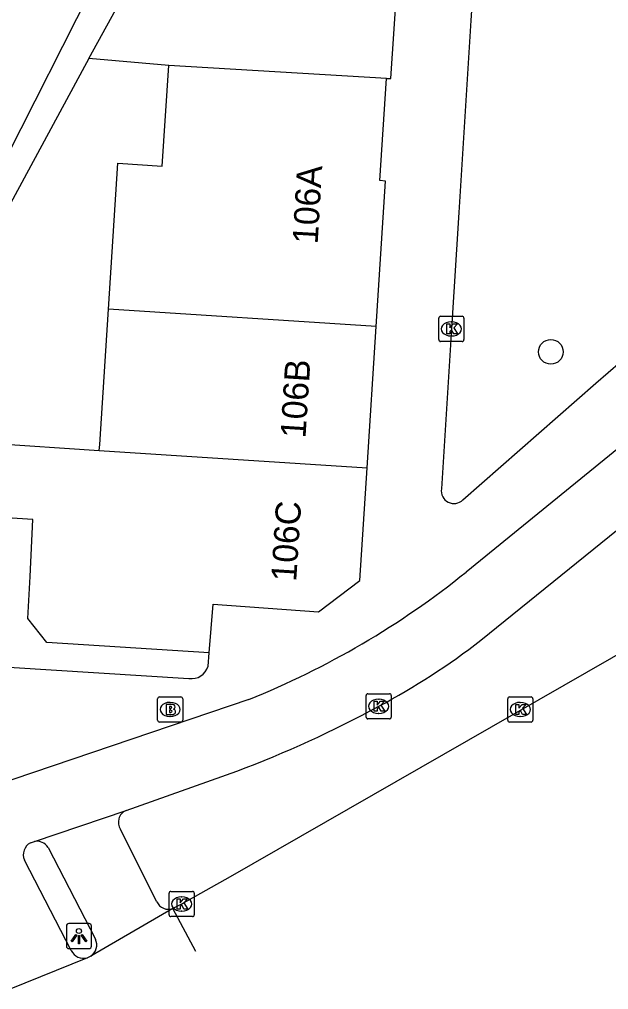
# Model space of a CAD drawing. Extents: x 159961 to 160856, y 382704 to 383353.
# Drawn here: x 160545.75 to 160569.17, y 382711.52 to 382750.05 of the extents above; entities that cross this region are included whole.
import ezdxf

# ---------------------------------------------------------------- set-up
doc = ezdxf.new("R2010")
doc.units = 0
for name, color, linetype in [('IMGEO_Boom', 7, 'Continuous'), ('IMGEO_Brandkraan', 7, 'Continuous'), ('IMGEO_Fietspad_gesloten', 7, 'Continuous'), ('IMGEO_Kolk', 7, 'Continuous'), ('IMGEO_Lichtpunt', 7, 'Continuous'), ('IMGEO_Pand', 7, 'Continuous'), ('IMGEO_Pand_nummerreeks', 7, 'Continuous'), ('IMGEO_Rijbaan_lokaal_gesloten', 7, 'Continuous'), ('IMGEO_Voetpad_open', 7, 'Continuous')]:
    doc.layers.add(name, color=color, linetype=linetype)

msp = doc.modelspace()

# ---------------------------------------------------------------- linework, layer by layer
at = {"layer": 'IMGEO_Boom'}
msp.add_circle((160566.873, 382736.846), 0.489, dxfattribs=at)
at = {"layer": 'IMGEO_Brandkraan'}
for p, q in [((160551.315, 382723.144), (160552.167, 382723.144)), ((160551.24, 382722.218), (160551.24, 382723.07)), ((160551.728, 382722.924), (160551.753, 382722.924)), ((160552.241, 382723.07), (160552.241, 382722.218)), ((160551.751, 382722.364), (160551.726, 382722.364)), ((160552.167, 382722.144), (160551.315, 382722.144))]:
    msp.add_line(p, q, dxfattribs=at)
for points in [[(160551.315, 382723.144), (160552.167, 382723.144)], [(160551.24, 382722.218), (160551.24, 382723.07)], [(160551.588, 382722.844), (160551.588, 382722.444), (160551.801, 382722.444)], [(160551.819, 382722.844), (160551.588, 382722.844)], [(160551.767, 382722.763), (160551.713, 382722.763), (160551.713, 382722.687)], [(160552.241, 382723.07), (160552.241, 382722.218)], [(160551.713, 382722.687), (160551.766, 382722.687)], [(160551.775, 382722.611), (160551.713, 382722.611), (160551.713, 382722.53)], [(160551.713, 382722.53), (160551.775, 382722.53)], [(160552.167, 382722.144), (160551.315, 382722.144)]]:
    msp.add_lwpolyline(points, dxfattribs=at)
for centre, radius, start, end in [((160551.317, 382723.068), 0.0765, 91.552, 178.448), ((160551.317, 382723.068), 0.0765, 91.552, 178.448), ((160552.165, 382723.068), 0.0765, 1.552, 88.448), ((160552.165, 382723.068), 0.0765, 1.552, 88.448), ((160551.768, 382722.725), 0.0379, 267.8285, 90.9355), ((160551.823, 382722.699), 0.145, 59.4692, 91.5367), ((160551.848, 382722.746), 0.0922, 285.5137, 58.1501), ((160551.776, 382722.57), 0.0404, 269.8759, 90.5077), ((160551.807, 382722.695), 0.251, 268.6676, 293.5347), ((160551.853, 382722.554), 0.105, 301.3115, 78.989), ((160551.317, 382722.22), 0.0765, 181.552, 268.448), ((160551.317, 382722.22), 0.0765, 181.552, 268.448), ((160552.165, 382722.22), 0.0765, 271.552, 358.448), ((160552.165, 382722.22), 0.0765, 271.552, 358.448)]:
    msp.add_arc(centre, radius, start, end, dxfattribs=at)
for centre, major_axis, ratio, start_param, end_param in [((160551.727, 382722.644), (-0.387, 0.002), 0.722429, 4.712389, 7.853982), ((160551.752, 382722.644), (-0.39, 0.002), 0.717154, 1.570796, 4.712389)]:
    msp.add_ellipse(centre, major_axis=major_axis, ratio=ratio, start_param=start_param, end_param=end_param, dxfattribs=at)
at = {"layer": 'IMGEO_Fietspad_gesloten'}
for points in [[(160579.704, 382739.971), (160571.274, 382734.411), (160563.508, 382728.101)], [(160564.089, 382725.394), (160572.382, 382732.089), (160574.211, 382733.38)], [(160554.866, 382723.034), (160541.601, 382718.558)], [(160549.988, 382718.627), (160554.394, 382720.196)], [(160546.35, 382717.404), (160549.988, 382718.627)], [(160546.188, 382717.349), (160546.35, 382717.404)], [(160547.813, 382713.074), (160545.95, 382716.662)]]:
    msp.add_lwpolyline(points, dxfattribs=at)
for centre, radius, start, end in [((160541.972, 382754.929), 34.403, 292.0121, 308.756), ((160546.643, 382747.925), 28.496, 298.0235, 307.7518), ((160538.317, 382762.865), 45.597, 290.6463, 298.4391), ((160546.439, 382716.877), 0.534, 118.0052, 203.7792), ((160548.297, 382713.29), 0.53, 204.0897, 286.8736)]:
    msp.add_arc(centre, radius, start, end, dxfattribs=at)
at = {"layer": 'IMGEO_Kolk'}
for p, q in [((160562.419, 382737.331), (160562.419, 382738.183)), ((160562.494, 382738.257), (160563.346, 382738.257)), ((160563.42, 382738.183), (160563.42, 382737.331)), ((160562.907, 382738.037), (160562.932, 382738.037)), ((160562.93, 382737.477), (160562.905, 382737.477)), ((160563.346, 382737.257), (160562.494, 382737.257)), ((160559.53, 382722.344), (160559.53, 382723.196)), ((160559.605, 382723.27), (160560.457, 382723.27)), ((160560.531, 382723.196), (160560.531, 382722.344)), ((160565.233, 382723.144), (160566.085, 382723.144)), ((160560.018, 382723.05), (160560.043, 382723.05)), ((160565.158, 382722.218), (160565.158, 382723.07)), ((160565.646, 382722.924), (160565.671, 382722.924)), ((160566.159, 382723.07), (160566.159, 382722.218)), ((160560.041, 382722.49), (160560.016, 382722.49)), ((160565.669, 382722.364), (160565.644, 382722.364)), ((160560.457, 382722.27), (160559.605, 382722.27)), ((160566.085, 382722.144), (160565.233, 382722.144)), ((160551.773, 382715.417), (160552.625, 382715.417)), ((160551.698, 382714.491), (160551.698, 382715.343)), ((160552.186, 382715.197), (160552.211, 382715.197)), ((160552.699, 382715.343), (160552.699, 382714.491)), ((160552.209, 382714.637), (160552.184, 382714.637)), ((160552.625, 382714.417), (160551.773, 382714.417))]:
    msp.add_line(p, q, dxfattribs=at)
for points in [[(160562.419, 382737.331), (160562.419, 382738.183)], [(160562.494, 382738.257), (160563.346, 382738.257)], [(160563.42, 382738.183), (160563.42, 382737.331)], [(160562.74, 382737.957), (160562.863, 382737.957), (160562.863, 382737.806), (160562.993, 382737.957), (160563.157, 382737.957), (160563.011, 382737.806), (160563.164, 382737.557), (160563.012, 382737.557), (160562.927, 382737.721), (160562.863, 382737.654), (160562.863, 382737.557), (160562.74, 382737.557), (160562.74, 382737.957)], [(160563.346, 382737.257), (160562.494, 382737.257)], [(160559.53, 382722.344), (160559.53, 382723.196)], [(160559.605, 382723.27), (160560.457, 382723.27)], [(160560.531, 382723.196), (160560.531, 382722.344)], [(160565.233, 382723.144), (160566.085, 382723.144)], [(160559.851, 382722.97), (160559.974, 382722.97), (160559.974, 382722.819), (160560.104, 382722.97), (160560.268, 382722.97), (160560.122, 382722.819), (160560.275, 382722.57), (160560.123, 382722.57), (160560.038, 382722.734), (160559.974, 382722.667), (160559.974, 382722.57), (160559.851, 382722.57), (160559.851, 382722.97)], [(160565.158, 382722.218), (160565.158, 382723.07)], [(160565.479, 382722.844), (160565.602, 382722.844), (160565.602, 382722.693), (160565.732, 382722.844), (160565.896, 382722.844), (160565.75, 382722.693), (160565.903, 382722.444), (160565.751, 382722.444), (160565.666, 382722.608), (160565.602, 382722.541), (160565.602, 382722.444), (160565.479, 382722.444), (160565.479, 382722.844)], [(160566.159, 382723.07), (160566.159, 382722.218)], [(160560.457, 382722.27), (160559.605, 382722.27)], [(160566.085, 382722.144), (160565.233, 382722.144)], [(160551.773, 382715.417), (160552.625, 382715.417)], [(160551.698, 382714.491), (160551.698, 382715.343)], [(160552.019, 382715.117), (160552.142, 382715.117), (160552.142, 382714.966), (160552.272, 382715.117), (160552.436, 382715.117), (160552.29, 382714.966), (160552.443, 382714.717), (160552.291, 382714.717), (160552.206, 382714.881), (160552.142, 382714.814), (160552.142, 382714.717), (160552.019, 382714.717), (160552.019, 382715.117)], [(160552.699, 382715.343), (160552.699, 382714.491)], [(160552.625, 382714.417), (160551.773, 382714.417)]]:
    msp.add_lwpolyline(points, dxfattribs=at)
for centre, start, end in [((160562.496, 382738.181), 91.552, 178.448), ((160562.496, 382738.181), 91.552, 178.448), ((160563.344, 382738.181), 1.552, 88.448), ((160563.344, 382738.181), 1.552, 88.448), ((160562.496, 382737.333), 181.552, 268.448), ((160562.496, 382737.333), 181.552, 268.448), ((160563.344, 382737.333), 271.552, 358.448), ((160563.344, 382737.333), 271.552, 358.448), ((160559.607, 382723.194), 91.552, 178.448), ((160559.607, 382723.194), 91.552, 178.448), ((160560.455, 382723.194), 1.552, 88.448), ((160560.455, 382723.194), 1.552, 88.448), ((160565.235, 382723.068), 91.552, 178.448), ((160565.235, 382723.068), 91.552, 178.448), ((160566.083, 382723.068), 1.552, 88.448), ((160566.083, 382723.068), 1.552, 88.448), ((160559.607, 382722.346), 181.552, 268.448), ((160559.607, 382722.346), 181.552, 268.448), ((160560.455, 382722.346), 271.552, 358.448), ((160560.455, 382722.346), 271.552, 358.448), ((160565.235, 382722.22), 181.552, 268.448), ((160565.235, 382722.22), 181.552, 268.448), ((160566.083, 382722.22), 271.552, 358.448), ((160566.083, 382722.22), 271.552, 358.448), ((160551.775, 382715.341), 91.552, 178.448), ((160551.775, 382715.341), 91.552, 178.448), ((160552.623, 382715.341), 1.552, 88.448), ((160552.623, 382715.341), 1.552, 88.448), ((160551.775, 382714.493), 181.552, 268.448), ((160551.775, 382714.493), 181.552, 268.448), ((160552.623, 382714.493), 271.552, 358.448), ((160552.623, 382714.493), 271.552, 358.448)]:
    msp.add_arc(centre, 0.0765, start, end, dxfattribs=at)
for centre, major_axis, ratio, start_param, end_param in [((160562.906, 382737.757), (-0.387, 0.002), 0.722429, 4.712389, 7.853982), ((160562.931, 382737.757), (-0.39, 0.002), 0.717154, 1.570796, 4.712389), ((160560.017, 382722.77), (-0.387, 0.002), 0.722429, 4.712389, 7.853982), ((160560.042, 382722.77), (-0.39, 0.002), 0.717154, 1.570796, 4.712389), ((160565.645, 382722.644), (-0.387, 0.002), 0.722429, 4.712389, 7.853982), ((160565.67, 382722.644), (-0.39, 0.002), 0.717154, 1.570796, 4.712389), ((160552.185, 382714.917), (-0.387, 0.002), 0.722429, 4.712389, 7.853982), ((160552.21, 382714.917), (-0.39, 0.002), 0.717154, 1.570796, 4.712389)]:
    msp.add_ellipse(centre, major_axis=major_axis, ratio=ratio, start_param=start_param, end_param=end_param, dxfattribs=at)
at = {"layer": 'IMGEO_Lichtpunt'}
for p, q in [((160547.616, 382714.047), (160547.616, 382713.24)), ((160547.616, 382714.047), (160547.616, 382713.24)), ((160548.518, 382714.142), (160547.71, 382714.142)), ((160548.518, 382714.142), (160547.71, 382714.142)), ((160548.612, 382713.24), (160548.612, 382714.047)), ((160548.612, 382713.24), (160548.612, 382714.047)), ((160547.71, 382713.146), (160548.518, 382713.146)), ((160547.71, 382713.146), (160548.518, 382713.146))]:
    msp.add_line(p, q, dxfattribs=at)
for points in [[(160547.99, 382713.711), (160548.029, 382713.683), (160547.841, 382713.421), (160547.803, 382713.448), (160547.99, 382713.711)], [(160548.092, 382713.663), (160548.139, 382713.663), (160548.139, 382713.341), (160548.092, 382713.341), (160548.092, 382713.663)], [(160548.202, 382713.683), (160548.24, 382713.71), (160548.427, 382713.448), (160548.388, 382713.42), (160548.202, 382713.683)]]:
    msp.add_lwpolyline(points, dxfattribs=at)
msp.add_circle((160548.115, 382713.845), 0.0994, dxfattribs=at)
for centre, start, end in [((160547.71, 382714.047), 90, 180), ((160547.71, 382714.047), 90, 180), ((160548.518, 382714.047), 0, 90), ((160548.518, 382714.047), 0, 90), ((160547.71, 382713.24), 180, 270), ((160547.71, 382713.24), 180, 270), ((160548.518, 382713.24), 270, 0), ((160548.518, 382713.24), 270, 360)]:
    msp.add_arc(centre, 0.0946, start, end, dxfattribs=at)
at = {"layer": 'IMGEO_Pand'}
for points in [[(160560.345, 382747.708), (160560.518, 382747.698), (160561.689, 382765.271)], [(160548.515, 382748.492), (160549.578, 382750.441)], [(160551.689, 382748.216), (160548.515, 382748.492)], [(160549.29, 382738.538), (160549.666, 382744.34), (160551.423, 382744.223), (160551.689, 382748.216)], [(160560.345, 382747.708), (160551.689, 382748.216)], [(160559.933, 382737.851), (160560.307, 382743.631), (160560.082, 382743.646), (160560.345, 382747.708)], [(160548.926, 382732.933), (160548.942, 382733.173), (160549.29, 382738.538)], [(160559.933, 382737.851), (160549.29, 382738.538)], [(160559.569, 382732.246), (160559.933, 382737.851)], [(160553.29, 382724.888), (160546.838, 382725.309), (160546.088, 382726.259), (160546.173, 382727.925), (160546.289, 382730.182), (160541.926, 382730.463), (160541.863, 382730.569), (160544.577, 382733.215), (160548.926, 382732.933)], [(160548.926, 382732.933), (160559.569, 382732.246)], [(160553.29, 382724.888), (160553.446, 382726.82), (160557.637, 382726.52), (160559.279, 382727.763), (160559.569, 382732.246)]]:
    msp.add_lwpolyline(points, dxfattribs=at)
at = {"layer": 'IMGEO_Rijbaan_lokaal_gesloten'}
for points in [[(160576.717, 382728.936), (160573.974, 382727.368), (160554.123, 382716.001), (160552.199, 382714.917), (160551.851, 382714.737)], [(160551.851, 382714.737), (160548.583, 382712.844)], [(160552.766, 382713.027), (160551.851, 382714.737)], [(160548.451, 382712.783), (160545.347, 382711.519)], [(160548.583, 382712.844), (160548.451, 382712.783)]]:
    msp.add_lwpolyline(points, dxfattribs=at)
at = {"layer": 'IMGEO_Voetpad_open'}
for points in [[(160500, 382786.837), (160511.443, 382799.049), (160528.6, 382782.973), (160538.139, 382774.036), (160539.262, 382772.17), (160542.977, 382767.126), (160550.236, 382754.458), (160543.577, 382741.333)], [(160564.482, 382761.76), (160563.998, 382754.722), (160563.965, 382754.206), (160563.698, 382750), (160563.213, 382742.378), (160562.919, 382737.759), (160562.523, 382731.401)], [(160548.515, 382748.492), (160544.411, 382740.949), (160544.056, 382739.042), (160543.456, 382735.821), (160536.151, 382728.593)], [(160563.378, 382730.969), (160568.656, 382735.599), (160570.623, 382737.301), (160572.484, 382738.845), (160575.78, 382741.584)], [(160536.151, 382728.593), (160540.052, 382724.65), (160552.483, 382723.877)], [(160553.247, 382724.366), (160553.29, 382724.888)], [(160551.214, 382715.01), (160549.768, 382717.879)], [(160546.892, 382717.161), (160548.77, 382713.526)]]:
    msp.add_lwpolyline(points, dxfattribs=at)
for centre, radius, start, end in [((160563.022, 382731.326), 0.504, 171.4484, 314.94), ((160552.595, 382724.543), 0.675, 260.444, 344.7988), ((160550.187, 382718.162), 0.506, 113.1922, 214.0287), ((160546.44, 382716.879), 0.533, 31.9863, 99.7166), ((160551.68, 382715.218), 0.511, 204.0847, 289.5181), ((160548.296, 382713.289), 0.529, 302.7669, 26.5665)]:
    msp.add_arc(centre, radius, start, end, dxfattribs=at)

# ---------------------------------------------------------------- texts
at = {"layer": 'IMGEO_Pand_nummerreeks'}
for s, rotation, p in [('106A', 86.5994, (160557.603, 382741.109)), ('106B', 86.2843, (160557.119, 382733.398)), ('106C', 86.2975, (160556.75, 382727.703))]:
    msp.add_text(s, height=1, rotation=rotation, dxfattribs=at).set_placement(p)

doc.saveas('drawing.dxf')
